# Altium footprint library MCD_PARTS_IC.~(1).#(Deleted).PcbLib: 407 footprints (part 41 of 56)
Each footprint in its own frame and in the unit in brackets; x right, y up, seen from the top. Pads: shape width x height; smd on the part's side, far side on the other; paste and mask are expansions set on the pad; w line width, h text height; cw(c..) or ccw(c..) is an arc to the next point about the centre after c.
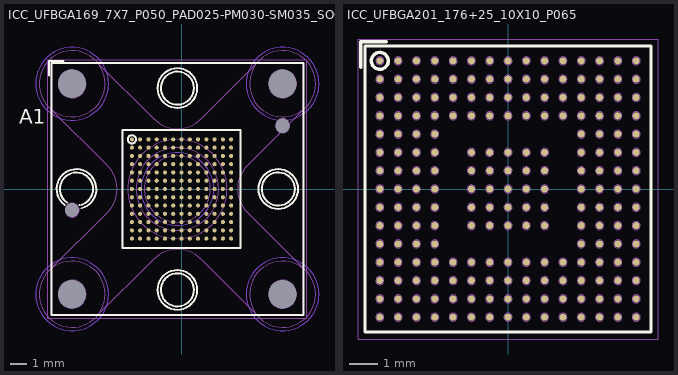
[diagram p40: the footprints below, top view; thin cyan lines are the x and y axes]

## ICC_UFBGA169_7X7_P050_PAD025-PM030-SM035_SOCKET_IRONWOOD_CS1627113MF_NM - duplicate1 [mm] "MCD-01902"
height 8.5
pads (175):
  round 0 hole 1.7 unplated mask+0.05: 0(-6.612,-6.362) 0(-6.612,6.363) 0(6.113,-6.362) 0(6.113,6.363)
  round 0 hole 0.85 unplated mask+0.05: 0(-6.612,-1.282) 0(6.113,3.823)
  round 0.25 smd paste+0.025 mask+0.05: A1(-3,3) A2(-2.5,3) A3(-2,3) A4(-1.5,3) A5(-1,3) A6(-0.5,3) A7(0,3) A8(0.5,3) A9(1,3) A10(1.5,3) A11(2,3) A12(2.5,3) A13(3,3) B1(-3,2.5) B2(-2.5,2.5) B3(-2,2.5) B4(-1.5,2.5) B5(-1,2.5) B6(-0.5,2.5) B7(0,2.5) B8(0.5,2.5) B9(1,2.5) B10(1.5,2.5) B11(2,2.5) B12(2.5,2.5) B13(3,2.5) C1(-3,2) C2(-2.5,2) C3(-2,2) C4(-1.5,2) C5(-1,2) C6(-0.5,2) C7(0,2) C8(0.5,2) C9(1,2) C10(1.5,2) C11(2,2) C12(2.5,2) C13(3,2) D1(-3,1.5) D2(-2.5,1.5) D3(-2,1.5) D4(-1.5,1.5) D5(-1,1.5) D6(-0.5,1.5) D7(0,1.5) D8(0.5,1.5) D9(1,1.5) D10(1.5,1.5) D11(2,1.5) D12(2.5,1.5) D13(3,1.5) E1(-3,1) E2(-2.5,1) E3(-2,1) E4(-1.5,1) E5(-1,1) E6(-0.5,1) E7(0,1) E8(0.5,1) E9(1,1) E10(1.5,1) E11(2,1) E12(2.5,1) E13(3,1) F1(-3,0.5) F2(-2.5,0.5) F3(-2,0.5) F4(-1.5,0.5) F5(-1,0.5) F6(-0.5,0.5) F7(0,0.5) F8(0.5,0.5) F9(1,0.5) F10(1.5,0.5) F11(2,0.5) F12(2.5,0.5) F13(3,0.5) G1(-3,0) G2(-2.5,0) G3(-2,0) G4(-1.5,0) G5(-1,0) G6(-0.5,0) G7(0,0) G8(0.5,0) G9(1,0) G10(1.5,0) G11(2,0) G12(2.5,0) G13(3,0) H1(-3,-0.5) H2(-2.5,-0.5) H3(-2,-0.5) H4(-1.5,-0.5) H5(-1,-0.5) H6(-0.5,-0.5) H7(0,-0.5) H8(0.5,-0.5) H9(1,-0.5) H10(1.5,-0.5) H11(2,-0.5) H12(2.5,-0.5) H13(3,-0.5) J1(-3,-1) J2(-2.5,-1) J3(-2,-1) J4(-1.5,-1) J5(-1,-1) J6(-0.5,-1) J7(0,-1) J8(0.5,-1) J9(1,-1) J10(1.5,-1) J11(2,-1) J12(2.5,-1) J13(3,-1) K1(-3,-1.5) K2(-2.5,-1.5) K3(-2,-1.5) K4(-1.5,-1.5) K5(-1,-1.5) K6(-0.5,-1.5) K7(0,-1.5) K8(0.5,-1.5) K9(1,-1.5) K10(1.5,-1.5) K11(2,-1.5) K12(2.5,-1.5) K13(3,-1.5) L1(-3,-2) L2(-2.5,-2) L3(-2,-2) L4(-1.5,-2) L5(-1,-2) L6(-0.5,-2) L7(0,-2) L8(0.5,-2) L9(1,-2) L10(1.5,-2) L11(2,-2) L12(2.5,-2) L13(3,-2) M1(-3,-2.5) M2(-2.5,-2.5) M3(-2,-2.5) M4(-1.5,-2.5) M5(-1,-2.5) M6(-0.5,-2.5) M7(0,-2.5) M8(0.5,-2.5) M9(1,-2.5) M10(1.5,-2.5) M11(2,-2.5) M12(2.5,-2.5) M13(3,-2.5) N1(-3,-3) N2(-2.5,-3) N3(-2,-3) N4(-1.5,-3) N5(-1,-3) N6(-0.5,-3) N7(0,-3) N8(0.5,-3) N9(1,-3) N10(1.5,-3) N11(2,-3) N12(2.5,-3) N13(3,-3)
Bottom Layer keep-out:
  circle w0.01: c-6.612,-6.362 r2.2
  circle w0.01: c6.113,-6.362 r2.2
  circle w0.01: c6.113,6.363 r2.2
  circle w0.01: c-0.25,0 r2.2
  circle w0.01: c-6.612,6.363 r2.2
Top Overlay:
  circle w0.12: c-0.25,-6.1 r1.2
  circle w0.12: c-0.25,-6.1 r1
  circle w0.12: c-0.25,6.1 r1.2
  circle w0.12: c-0.25,6.1 r1
  circle w0.12: c5.85,0 r1
  circle w0.12: c5.85,0 r1.2
  circle w0.12: c-3,3 r0.25
  circle w0.1: c-3,3 r0.25
  lines w0.12: -8,6.875 -8,7.75 -7.125,7.75 ; -7.066,-0.963 cw(c-6.35,0) -6.059,-1.164 ; -6.918,-0.823 cw(c-6.35,0) -6.154,-0.981 ; -7.862,-7.612 -7.862,7.613 7.363,7.613 7.363,-7.612 -7.862,-7.612 ; -3.575,-3.575 3.575,-3.575 3.575,3.575 -3.575,3.575 -3.575,-3.575
  text "A1" at -9.825,3.65 h1.5
Bottom Overlay:
  circle w0.12: c-6.612,6.363 r2
  circle w0.12: c6.113,6.363 r2
  circle w0.12: c-0.25,0 r2
  circle w0.12: c6.113,-6.362 r2
  circle w0.12: c-6.612,-6.362 r2
M6-Bottom Constraints:
  text "MAX / HEIGHT  / AUTHORIZED / 1.5mm" at 0,0 h0.8
  text "MAX / HEIGHT  / AUTHORIZED / 1.5mm" at 0,0 h0.8
  text "MAX / HEIGHT  / AUTHORIZED / 1.5mm" at 0,0 h0.8
  text "MAX / HEIGHT  / AUTHORIZED / 1.5mm" at 0,0 h0.8
M14-Top Assembly:
  circle w0.01: c-3,3 r0.25
  circle w0.01: c-0.25,0 r3
  circle w0.01: c-0.25,0 r2.5
  circle w0.01: c5.85,0 r1.2
  circle w0.01: c5.85,0 r1
  circle w0.01: c-0.25,6.1 r1
  circle w0.01: c-0.25,6.1 r1.2
  circle w0.01: c-6.35,0 r1
  circle w0.01: c-6.35,0 r1.2
  circle w0.01: c-0.25,-6.1 r1
  circle w0.01: c-0.25,-6.1 r1.2
  lines w0.01: -7.862,-7.612 7.363,-7.612 7.363,7.613 -7.862,7.613 -7.862,-7.612 ; -3.575,-3.575 -3.575,3.575 3.575,3.575 3.575,-3.575 -3.575,-3.575
  text "'.Designator'" at -2,-0.5 h0.75
  text "A1" at -3.4,3.05 h0.5
M15-Bottom Assembly:
  circle w0.01: c6.113,3.823 r0.425
  circle w0.01: c-6.612,-1.282 r0.425
  circle w0.01: c6.113,-6.362 r0.85
  circle w0.01: c-6.612,-6.362 r0.85
  circle w0.01: c6.113,6.363 r0.85
  circle w0.01: c-6.612,6.363 r0.85
  circle w0.01: c-0.25,0 r2
  circle w0.01: c-6.612,6.363 r2
  circle w0.01: c6.113,6.363 r2
  circle w0.01: c6.113,-6.362 r2
  circle w0.01: c-6.612,-6.362 r2
  lines w0.01: -7.862,4.8 -4.522,1.46 ; -5.05,-7.612 -1.71,-4.272 cw(c-0.25,-5.64) 1.21,-4.273 4.555,-7.617 ; -4.522,-1.46 -7.867,-4.805 ; -4.523,-1.46 ccw(c-5.89,0) -4.523,1.46 ; 4.022,-1.46 7.363,-4.8 ; 4.022,1.46 7.368,4.805 ; 4.023,-1.46 cw(c5.39,0) 4.023,1.46 ; 4.55,7.613 1.21,4.272 cw(c-0.25,5.64) -1.71,4.273 -5.055,7.618 ; -7.867,-4.805 -7.867,-4.805 ; -5.055,7.618 -5.055,7.618 ; 4.555,-7.617 4.555,-7.617 ; 7.368,4.805 7.368,4.805
M16-Top Courtyard:
  lines w0.01: -8.075,-7.825 -8.075,7.825 7.575,7.825 7.575,-7.825 -8.075,-7.825
M17-Bottom Courtyard:
  circle w0.01: c-6.612,-6.362 r2
  circle w0.01: c6.113,-6.362 r2
  circle w0.01: c6.113,6.363 r2
  circle w0.01: c-6.612,6.363 r2
  circle w0.01: c-0.25,0 r2
  lines w0.01: -7.862,4.8 -4.522,1.46 ; -5.05,-7.612 -1.71,-4.272 cw(c-0.25,-5.64) 1.21,-4.273 4.555,-7.617 ; -4.522,-1.46 -7.867,-4.805 ; -4.523,-1.46 ccw(c-5.89,0) -4.523,1.46 ; 4.022,-1.46 7.363,-4.8 ; 4.022,1.46 7.368,4.805 ; 4.023,-1.46 cw(c5.39,0) 4.023,1.46 ; 4.55,7.613 1.21,4.272 cw(c-0.25,5.64) -1.71,4.273 -5.055,7.618 ; -7.867,-4.805 -7.867,-4.805 ; -5.055,7.618 -5.055,7.618 ; 4.555,-7.617 4.555,-7.617 ; 7.368,4.805 7.368,4.805
  text "MAX / HEIGHT  / AUTHORIZED / 1.5mm" at 0,0 h0.8
  text "MAX / HEIGHT  / AUTHORIZED / 1.5mm" at 0,0 h0.8
  text "MAX / HEIGHT  / AUTHORIZED / 1.5mm" at 0,0 h0.8
  text "MAX / HEIGHT  / AUTHORIZED / 1.5mm" at 0,0 h0.8
3D body: height 0.61, standoff 0.6, extent -3.298,2.701 -2.7,3.299
3D body: height 0.25, standoff -0.05, extent -2.136,1.857 -1.855,2.143
3D body: height 0.25, standoff -0.05, extent -1.636,1.857 -1.355,2.143
3D body: height 0.25, standoff -0.05, extent -0.636,1.857 -0.355,2.143
3D body: height 0.25, standoff -0.05, extent -0.136,1.857 0.145,2.143
3D body: height 0.25, standoff -0.05, extent 0.864,1.857 1.145,2.143
3D body: height 0.25, standoff -0.05, extent 1.364,1.857 1.645,2.143
3D body: height 0.25, standoff -0.05, extent 1.864,1.857 2.145,2.143
3D body: height 0.25, standoff -0.05, extent -2.136,1.357 -1.855,1.643
3D body: height 0.25, standoff -0.05, extent -1.636,1.357 -1.355,1.643
3D body: height 0.25, standoff -0.05, extent -1.136,1.357 -0.855,1.643
3D body: height 0.25, standoff -0.05, extent -0.636,1.357 -0.355,1.643
3D body: height 0.25, standoff -0.05, extent -0.136,1.357 0.145,1.643
3D body: height 0.25, standoff -0.05, extent 0.364,1.357 0.645,1.643
3D body: height 0.25, standoff -0.05, extent 0.864,1.357 1.145,1.643
3D body: height 0.25, standoff -0.05, extent 1.364,1.357 1.645,1.643
3D body: height 0.25, standoff -0.05, extent 1.864,1.357 2.145,1.643
3D body: height 0.25, standoff -0.05, extent -1.136,0.857 -0.855,1.143
3D body: height 0.25, standoff -0.05, extent 0.364,0.857 0.645,1.143
3D body: height 0.25, standoff -0.05, extent 1.864,0.357 2.145,0.643
3D body: height 0.25, standoff -0.05, extent 1.364,0.357 1.645,0.643
3D body: height 0.25, standoff -0.05, extent 0.864,0.357 1.145,0.643
3D body: height 0.25, standoff -0.05, extent 0.364,0.357 0.645,0.643
3D body: height 0.25, standoff -0.05, extent -0.136,0.357 0.145,0.643
3D body: height 0.25, standoff -0.05, extent -0.636,0.357 -0.355,0.643
3D body: height 0.25, standoff -0.05, extent -1.136,0.357 -0.855,0.643
3D body: height 0.25, standoff -0.05, extent -1.636,0.357 -1.355,0.643
3D body: height 0.25, standoff -0.05, extent 1.364,0.857 1.645,1.143
3D body: height 0.25, standoff -0.05, extent 0.864,0.857 1.145,1.143
3D body: height 0.25, standoff -0.05, extent -0.136,0.857 0.145,1.143
3D body: height 0.25, standoff -0.05, extent -0.636,0.857 -0.355,1.143
3D body: height 0.25, standoff -0.05, extent -1.636,0.857 -1.355,1.143
3D body: height 0.25, standoff -0.05, extent -2.136,0.857 -1.855,1.143
3D body: height 0.25, standoff -0.05, extent -1.636,-1.143 -1.355,-0.857
3D body: height 0.25, standoff -0.05, extent -0.636,-1.143 -0.355,-0.857
3D body: height 0.25, standoff -0.05, extent -0.136,-1.143 0.145,-0.857
3D body: height 0.25, standoff -0.05, extent 0.864,-1.143 1.145,-0.857
3D body: height 0.25, standoff -0.05, extent 1.364,-1.143 1.645,-0.857
3D body: height 0.25, standoff -0.05, extent 1.864,-1.143 2.145,-0.857
3D body: height 0.25, standoff -0.05, extent -2.136,-1.643 -1.855,-1.357
3D body: height 0.25, standoff -0.05, extent -1.636,-1.643 -1.355,-1.357
3D body: height 0.25, standoff -0.05, extent -1.136,-1.643 -0.855,-1.357
3D body: height 0.25, standoff -0.05, extent -0.636,-1.643 -0.355,-1.357
3D body: height 0.25, standoff -0.05, extent -0.136,-1.643 0.145,-1.357
3D body: height 0.25, standoff -0.05, extent 0.364,-1.643 0.645,-1.357
3D body: height 0.25, standoff -0.05, extent 0.864,-1.643 1.145,-1.357
3D body: height 0.25, standoff -0.05, extent 1.364,-1.643 1.645,-1.357
3D body: height 0.25, standoff -0.05, extent 1.864,-1.643 2.145,-1.357
3D body: height 0.25, standoff -0.05, extent 0.364,-1.143 0.645,-0.857
3D body: height 0.25, standoff -0.05, extent -1.136,-1.143 -0.855,-0.857
3D body: height 0.25, standoff -0.05, extent -1.136,-0.143 -0.855,0.143
3D body: height 0.25, standoff -0.05, extent 0.364,-0.143 0.645,0.143
3D body: height 0.25, standoff -0.05, extent 1.364,-0.643 1.645,-0.357
3D body: height 0.25, standoff -0.05, extent 0.864,-0.643 1.145,-0.357
3D body: height 0.25, standoff -0.05, extent 0.364,-0.643 0.645,-0.357
3D body: height 0.25, standoff -0.05, extent -0.136,-0.643 0.145,-0.357
3D body: height 0.25, standoff -0.05, extent -0.636,-0.643 -0.355,-0.357
3D body: height 0.25, standoff -0.05, extent -1.136,-0.643 -0.855,-0.357
3D body: height 0.25, standoff -0.05, extent -1.636,-0.643 -1.355,-0.357
3D body: height 0.25, standoff -0.05, extent -2.136,-0.643 -1.855,-0.357
3D body: height 0.25, standoff -0.05, extent 1.864,-0.143 2.145,0.143
3D body: height 0.25, standoff -0.05, extent 1.364,-0.143 1.645,0.143
3D body: height 0.25, standoff -0.05, extent 0.864,-0.143 1.145,0.143
3D body: height 0.25, standoff -0.05, extent -0.136,-0.143 0.145,0.143
3D body: height 0.25, standoff -0.05, extent -0.636,-0.143 -0.355,0.143
3D body: height 0.25, standoff -0.05, extent -1.636,-0.143 -1.355,0.143
3D body: height 0.25, standoff -0.05, extent -2.136,-0.143 -1.855,0.143
3D body: height 0.25, standoff -0.05, extent 1.864,-2.143 2.145,-1.857
3D body: height 0.25, standoff -0.05, extent 1.364,-2.143 1.645,-1.857
3D body: height 0.25, standoff -0.05, extent 0.364,-2.143 0.645,-1.857
3D body: height 0.25, standoff -0.05, extent -0.136,-2.143 0.145,-1.857
3D body: height 0.25, standoff -0.05, extent -1.136,-2.143 -0.855,-1.857
3D body: height 0.25, standoff -0.05, extent -1.636,-2.143 -1.355,-1.857
3D body: height 0.25, standoff -0.05, extent -2.136,-2.143 -1.855,-1.857
3D body: height 0.25, standoff -0.05, extent -1.136,1.857 -0.855,2.143
3D body: height 0.25, standoff -0.05, extent 0.364,1.857 0.645,2.143
3D body: height 0.25, standoff -0.05, extent -2.136,0.357 -1.855,0.643
3D body: height 0.25, standoff -0.05, extent 1.864,0.857 2.145,1.143
3D body: height 0.25, standoff -0.05, extent 1.864,-0.643 2.145,-0.357
3D body: height 0.25, standoff -0.05, extent -2.136,-1.143 -1.855,-0.857
3D body: height 0.25, standoff -0.05, extent -2.636,1.857 -2.355,2.143
3D body: height 0.25, standoff -0.05, extent -3.136,1.857 -2.855,2.143
3D body: height 0.25, standoff -0.05, extent 2.364,1.857 2.645,2.143
3D body: height 0.25, standoff -0.05, extent 2.864,1.857 3.145,2.143
3D body: height 0.25, standoff -0.05, extent -0.136,2.357 0.145,2.643
3D body: height 0.25, standoff -0.05, extent -0.136,2.857 0.145,3.143
3D body: height 0.25, standoff -0.05, extent -0.136,-2.643 0.145,-2.357
3D body: height 0.25, standoff -0.05, extent -0.136,-3.143 0.145,-2.857
3D body: height 0.25, standoff -0.05, extent -0.636,-2.143 -0.355,-1.857
3D body: height 0.25, standoff -0.05, extent 0.864,-2.143 1.145,-1.857
3D body: height 0.25, standoff -0.05, extent 2.864,1.357 3.145,1.643
3D body: height 0.25, standoff -0.05, extent 2.364,1.357 2.645,1.643
3D body: height 0.25, standoff -0.05, extent 2.864,0.857 3.145,1.143
3D body: height 0.25, standoff -0.05, extent 2.364,0.857 2.645,1.143
3D body: height 0.25, standoff -0.05, extent 2.864,0.357 3.145,0.643
3D body: height 0.25, standoff -0.05, extent 2.364,0.357 2.645,0.643
3D body: height 0.25, standoff -0.05, extent 2.864,-0.143 3.145,0.143
3D body: height 0.25, standoff -0.05, extent 2.364,-0.143 2.645,0.143
3D body: height 0.25, standoff -0.05, extent 2.864,-0.643 3.145,-0.357
3D body: height 0.25, standoff -0.05, extent 2.364,-0.643 2.645,-0.357
3D body: height 0.25, standoff -0.05, extent 2.864,-1.143 3.145,-0.857
3D body: height 0.25, standoff -0.05, extent 2.364,-1.143 2.645,-0.857
3D body: height 0.25, standoff -0.05, extent 2.864,-1.643 3.145,-1.357
3D body: height 0.25, standoff -0.05, extent 2.364,-1.643 2.645,-1.357
3D body: height 0.25, standoff -0.05, extent 2.864,-2.143 3.145,-1.857
3D body: height 0.25, standoff -0.05, extent 2.364,-2.143 2.645,-1.857
3D body: height 0.25, standoff -0.05, extent -2.636,1.357 -2.355,1.643
3D body: height 0.25, standoff -0.05, extent -3.136,1.357 -2.855,1.643
3D body: height 0.25, standoff -0.05, extent -2.636,0.857 -2.355,1.143
3D body: height 0.25, standoff -0.05, extent -3.136,0.857 -2.855,1.143
3D body: height 0.25, standoff -0.05, extent -2.636,0.357 -2.355,0.643
3D body: height 0.25, standoff -0.05, extent -3.136,0.357 -2.855,0.643
3D body: height 0.25, standoff -0.05, extent -2.636,-0.143 -2.355,0.143
3D body: height 0.25, standoff -0.05, extent -3.136,-0.143 -2.855,0.143
3D body: height 0.25, standoff -0.05, extent -2.636,-0.643 -2.355,-0.357
3D body: height 0.25, standoff -0.05, extent -3.136,-0.643 -2.855,-0.357
3D body: height 0.25, standoff -0.05, extent -2.636,-1.143 -2.355,-0.857
3D body: height 0.25, standoff -0.05, extent -3.136,-1.143 -2.855,-0.857
3D body: height 0.25, standoff -0.05, extent -2.636,-1.643 -2.355,-1.357
3D body: height 0.25, standoff -0.05, extent -3.136,-1.643 -2.855,-1.357
3D body: height 0.25, standoff -0.05, extent -2.636,-2.143 -2.355,-1.857
3D body: height 0.25, standoff -0.05, extent -3.136,-2.143 -2.855,-1.857
3D body: height 0.25, standoff -0.05, extent -3.136,2.357 -2.855,2.643
3D body: height 0.25, standoff -0.05, extent -2.636,2.357 -2.355,2.643
3D body: height 0.25, standoff -0.05, extent -1.136,2.357 -0.855,2.643
3D body: height 0.25, standoff -0.05, extent -0.636,2.357 -0.355,2.643
3D body: height 0.25, standoff -0.05, extent -1.636,2.357 -1.355,2.643
3D body: height 0.25, standoff -0.05, extent -2.136,2.357 -1.855,2.643
3D body: height 0.25, standoff -0.05, extent -3.136,2.857 -2.855,3.143
3D body: height 0.25, standoff -0.05, extent -2.636,2.857 -2.355,3.143
3D body: height 0.25, standoff -0.05, extent -1.136,2.857 -0.855,3.143
3D body: height 0.25, standoff -0.05, extent -0.636,2.857 -0.355,3.143
3D body: height 0.25, standoff -0.05, extent -1.636,2.857 -1.355,3.143
3D body: height 0.25, standoff -0.05, extent -2.136,2.857 -1.855,3.143
3D body: height 0.25, standoff -0.05, extent 0.364,2.357 0.645,2.643
3D body: height 0.25, standoff -0.05, extent 0.864,2.357 1.145,2.643
3D body: height 0.25, standoff -0.05, extent 2.364,2.357 2.645,2.643
3D body: height 0.25, standoff -0.05, extent 2.864,2.357 3.145,2.643
3D body: height 0.25, standoff -0.05, extent 1.864,2.357 2.145,2.643
3D body: height 0.25, standoff -0.05, extent 1.364,2.357 1.645,2.643
3D body: height 0.25, standoff -0.05, extent 0.364,2.857 0.645,3.143
3D body: height 0.25, standoff -0.05, extent 0.864,2.857 1.145,3.143
3D body: height 0.25, standoff -0.05, extent 2.364,2.857 2.645,3.143
3D body: height 0.25, standoff -0.05, extent 2.864,2.857 3.145,3.143
3D body: height 0.25, standoff -0.05, extent 1.864,2.857 2.145,3.143
3D body: height 0.25, standoff -0.05, extent 1.364,2.857 1.645,3.143
3D body: height 0.25, standoff -0.05, extent -3.136,-2.643 -2.855,-2.357
3D body: height 0.25, standoff -0.05, extent -2.636,-2.643 -2.355,-2.357
3D body: height 0.25, standoff -0.05, extent -1.136,-2.643 -0.855,-2.357
3D body: height 0.25, standoff -0.05, extent -0.636,-2.643 -0.355,-2.357
3D body: height 0.25, standoff -0.05, extent -1.636,-2.643 -1.355,-2.357
3D body: height 0.25, standoff -0.05, extent -2.136,-2.643 -1.855,-2.357
3D body: height 0.25, standoff -0.05, extent -3.136,-3.143 -2.855,-2.857
3D body: height 0.25, standoff -0.05, extent -2.636,-3.143 -2.355,-2.857
3D body: height 0.25, standoff -0.05, extent -1.136,-3.143 -0.855,-2.857
3D body: height 0.25, standoff -0.05, extent -0.636,-3.143 -0.355,-2.857
3D body: height 0.25, standoff -0.05, extent -1.636,-3.143 -1.355,-2.857
3D body: height 0.25, standoff -0.05, extent -2.136,-3.143 -1.855,-2.857
3D body: height 0.25, standoff -0.05, extent 0.364,-2.643 0.645,-2.357
3D body: height 0.25, standoff -0.05, extent 0.864,-2.643 1.145,-2.357
3D body: height 0.25, standoff -0.05, extent 2.364,-2.643 2.645,-2.357
3D body: height 0.25, standoff -0.05, extent 2.864,-2.643 3.145,-2.357
3D body: height 0.25, standoff -0.05, extent 1.864,-2.643 2.145,-2.357
3D body: height 0.25, standoff -0.05, extent 1.364,-2.643 1.645,-2.357
3D body: height 0.25, standoff -0.05, extent 0.364,-3.143 0.645,-2.857
3D body: height 0.25, standoff -0.05, extent 0.864,-3.143 1.145,-2.857
3D body: height 0.25, standoff -0.05, extent 2.364,-3.143 2.645,-2.857
3D body: height 0.25, standoff -0.05, extent 2.864,-3.143 3.145,-2.857
3D body: height 0.25, standoff -0.05, extent 1.864,-3.143 2.145,-2.857
3D body: height 0.25, standoff -0.05, extent 1.364,-3.143 1.645,-2.857
3D body: height 0.6, standoff 0.15, extent -3.5,-3.5 3.5,3.5

## ICC_UFBGA201_176+25_10X10_P065 [mm]
height 0.6
pads (201):
  round 0.25 smd mask+0.038: A1(-4.55,4.55) A2(-3.9,4.55) A3(-3.25,4.55) A4(-2.6,4.55) A5(-1.95,4.55) A6(-1.3,4.55) A7(-0.65,4.55) A8(0,4.55) A9(0.65,4.55) A10(1.3,4.55) A11(1.95,4.55) A12(2.6,4.55) A13(3.25,4.55) A14(3.9,4.55) A15(4.55,4.55) B1(-4.55,3.9) B2(-3.9,3.9) B3(-3.25,3.9) B4(-2.6,3.9) B5(-1.95,3.9) B6(-1.3,3.9) B7(-0.65,3.9) B8(0,3.9) B9(0.65,3.9) B10(1.3,3.9) B11(1.95,3.9) B12(2.6,3.9) B13(3.25,3.9) B14(3.9,3.9) B15(4.55,3.9) C1(-4.55,3.25) C2(-3.9,3.25) C3(-3.25,3.25) C4(-2.6,3.25) C5(-1.95,3.25) C6(-1.3,3.25) C7(-0.65,3.25) C8(0,3.25) C9(0.65,3.25) C10(1.3,3.25) C11(1.95,3.25) C12(2.6,3.25) C13(3.25,3.25) C14(3.9,3.25) C15(4.55,3.25) D1(-4.55,2.6) D2(-3.9,2.6) D3(-3.25,2.6) D4(-2.6,2.6) D5(-1.95,2.6) D6(-1.3,2.6) D7(-0.65,2.6) D8(0,2.6) D9(0.65,2.6) D10(1.3,2.6) D11(1.95,2.6) D12(2.6,2.6) D13(3.25,2.6) D14(3.9,2.6) D15(4.55,2.6) E1(-4.55,1.95) E2(-3.9,1.95) E3(-3.25,1.95) E4(-2.6,1.95) E12(2.6,1.95) E13(3.25,1.95) E14(3.9,1.95) E15(4.55,1.95) F1(-4.55,1.3) F2(-3.9,1.3) F3(-3.25,1.3) F4(-2.6,1.3) F6(-1.3,1.3) F7(-0.65,1.3) F8(0,1.3) F9(0.65,1.3) F10(1.3,1.3) F12(2.6,1.3) F13(3.25,1.3) F14(3.9,1.3) F15(4.55,1.3) G1(-4.55,0.65) G2(-3.9,0.65) G3(-3.25,0.65) G4(-2.6,0.65) G6(-1.3,0.65) G7(-0.65,0.65) G8(0,0.65) G9(0.65,0.65) G10(1.3,0.65) G12(2.6,0.65) G13(3.25,0.65) G14(3.9,0.65) G15(4.55,0.65) H1(-4.55,0) H2(-3.9,0) H3(-3.25,0) H4(-2.6,0) H6(-1.3,0) H7(-0.65,0) H8(0,0) H9(0.65,0) H10(1.3,0) H12(2.6,0) H13(3.25,0) H14(3.9,0) H15(4.55,0) J1(-4.55,-0.65) J2(-3.9,-0.65) J3(-3.25,-0.65) J4(-2.6,-0.65) J6(-1.3,-0.65) J7(-0.65,-0.65) J8(0,-0.65) J9(0.65,-0.65) J10(1.3,-0.65) J12(2.6,-0.65) J13(3.25,-0.65) J14(3.9,-0.65) J15(4.55,-0.65) K1(-4.55,-1.3) K2(-3.9,-1.3) K3(-3.25,-1.3) K4(-2.6,-1.3) K6(-1.3,-1.3) K7(-0.65,-1.3) K8(0,-1.3) K9(0.65,-1.3) K10(1.3,-1.3) K12(2.6,-1.3) K13(3.25,-1.3) K14(3.9,-1.3) K15(4.55,-1.3) L1(-4.55,-1.95) L2(-3.9,-1.95) L3(-3.25,-1.95) L4(-2.6,-1.95) L12(2.6,-1.95) L13(3.25,-1.95) L14(3.9,-1.95) L15(4.55,-1.95) M1(-4.55,-2.6) M2(-3.9,-2.6) M3(-3.25,-2.6) M4(-2.6,-2.6) M5(-1.95,-2.6) M6(-1.3,-2.6) M7(-0.65,-2.6) M8(0,-2.6) M9(0.65,-2.6) M10(1.3,-2.6) M11(1.95,-2.6) M12(2.6,-2.6) M13(3.25,-2.6) M14(3.9,-2.6) M15(4.55,-2.6) N1(-4.55,-3.25) N2(-3.9,-3.25) N3(-3.25,-3.25) N4(-2.6,-3.25) N5(-1.95,-3.25) N6(-1.3,-3.25) N7(-0.65,-3.25) N8(0,-3.25) N9(0.65,-3.25) N10(1.3,-3.25) N11(1.95,-3.25) N12(2.6,-3.25) N13(3.25,-3.25) N14(3.9,-3.25) N15(4.55,-3.25) P1(-4.55,-3.9) P2(-3.9,-3.9) P3(-3.25,-3.9) P4(-2.6,-3.9) P5(-1.95,-3.9) P6(-1.3,-3.9) P7(-0.65,-3.9) P8(0,-3.9) P9(0.65,-3.9) P10(1.3,-3.9) P11(1.95,-3.9) P12(2.6,-3.9) P13(3.25,-3.9) P14(3.9,-3.9) P15(4.55,-3.9) R1(-4.55,-4.55) R2(-3.9,-4.55) R3(-3.25,-4.55) R4(-2.6,-4.55) R5(-1.95,-4.55) R6(-1.3,-4.55) R7(-0.65,-4.55) R8(0,-4.55) R9(0.65,-4.55) R10(1.3,-4.55) R11(1.95,-4.55) R12(2.6,-4.55) R13(3.25,-4.55) R14(3.9,-4.55) R15(4.55,-4.55)
Top Overlay:
  circle w0.12: c-4.55,4.55 r0.3
  lines w0.12: -5.225,4.325 -5.225,5.225 -4.325,5.225 ; -5.075,-5.075 5.075,-5.075 5.075,5.075 -5.075,5.075 -5.075,-5.075
M14-Top Assembly:
  drawing of 205 lines, arcs and shapes, not listed
  text "A1" at -4.9,4.4 h0.75
  text "'.Designator'" at 0,0 h0.75
M16-Top Courtyard:
  lines w0.01: -5.325,-5.325 5.325,-5.325 5.325,5.325 -5.325,5.325 -5.325,-5.325
3D body: height 0.61, standoff 0.6, extent -4.798,4.301 -4.3,4.8
3D body: height 0.6, standoff 0.15, extent -5.075,-5.075 5.075,5.075
3D body: height 0.25, standoff -0.05, extent -4.036,4.407 -3.755,4.693
3D body: height 0.25, standoff -0.05, extent -4.686,4.407 -4.405,4.693
3D body: height 0.25, standoff -0.05, extent -3.386,4.407 -3.105,4.693
3D body: height 0.25, standoff -0.05, extent -2.736,4.407 -2.455,4.693
3D body: height 0.25, standoff -0.05, extent -2.086,4.407 -1.805,4.693
3D body: height 0.25, standoff -0.05, extent -1.436,4.407 -1.155,4.693
3D body: height 0.25, standoff -0.05, extent -0.786,4.407 -0.505,4.693
3D body: height 0.25, standoff -0.05, extent -0.136,4.407 0.145,4.693
3D body: height 0.25, standoff -0.05, extent 0.514,4.407 0.795,4.693
3D body: height 0.25, standoff -0.05, extent 1.164,4.407 1.445,4.693
3D body: height 0.25, standoff -0.05, extent 1.814,4.407 2.095,4.693
3D body: height 0.25, standoff -0.05, extent 2.464,4.407 2.745,4.693
3D body: height 0.25, standoff -0.05, extent 3.114,4.407 3.395,4.693
3D body: height 0.25, standoff -0.05, extent 3.764,4.407 4.045,4.693
3D body: height 0.25, standoff -0.05, extent 4.414,4.407 4.695,4.693
3D body: height 0.25, standoff -0.05, extent 4.414,3.757 4.695,4.043
3D body: height 0.25, standoff -0.05, extent 3.764,3.757 4.045,4.043
3D body: height 0.25, standoff -0.05, extent 3.114,3.757 3.395,4.043
3D body: height 0.25, standoff -0.05, extent 2.464,3.757 2.745,4.043
3D body: height 0.25, standoff -0.05, extent 1.814,3.757 2.095,4.043
3D body: height 0.25, standoff -0.05, extent 1.164,3.757 1.445,4.043
3D body: height 0.25, standoff -0.05, extent 0.514,3.757 0.795,4.043
3D body: height 0.25, standoff -0.05, extent -0.136,3.757 0.145,4.043
3D body: height 0.25, standoff -0.05, extent -0.786,3.757 -0.505,4.043
3D body: height 0.25, standoff -0.05, extent -1.436,3.757 -1.155,4.043
3D body: height 0.25, standoff -0.05, extent -2.086,3.757 -1.805,4.043
3D body: height 0.25, standoff -0.05, extent -2.736,3.757 -2.455,4.043
3D body: height 0.25, standoff -0.05, extent -3.386,3.757 -3.105,4.043
3D body: height 0.25, standoff -0.05, extent -4.686,3.757 -4.405,4.043
3D body: height 0.25, standoff -0.05, extent -4.036,3.757 -3.755,4.043
3D body: height 0.25, standoff -0.05, extent 4.414,3.107 4.695,3.393
3D body: height 0.25, standoff -0.05, extent 3.764,3.107 4.045,3.393
3D body: height 0.25, standoff -0.05, extent 3.114,3.107 3.395,3.393
3D body: height 0.25, standoff -0.05, extent 2.464,3.107 2.745,3.393
3D body: height 0.25, standoff -0.05, extent 1.814,3.107 2.095,3.393
3D body: height 0.25, standoff -0.05, extent 1.164,3.107 1.445,3.393
3D body: height 0.25, standoff -0.05, extent 0.514,3.107 0.795,3.393
3D body: height 0.25, standoff -0.05, extent -0.136,3.107 0.145,3.393
3D body: height 0.25, standoff -0.05, extent -0.786,3.107 -0.505,3.393
3D body: height 0.25, standoff -0.05, extent -1.436,3.107 -1.155,3.393
3D body: height 0.25, standoff -0.05, extent -2.086,3.107 -1.805,3.393
3D body: height 0.25, standoff -0.05, extent -2.736,3.107 -2.455,3.393
3D body: height 0.25, standoff -0.05, extent -3.386,3.107 -3.105,3.393
3D body: height 0.25, standoff -0.05, extent -4.686,3.107 -4.405,3.393
3D body: height 0.25, standoff -0.05, extent -4.036,3.107 -3.755,3.393
3D body: height 0.25, standoff -0.05, extent 4.414,2.457 4.695,2.743
3D body: height 0.25, standoff -0.05, extent 3.764,2.457 4.045,2.743
3D body: height 0.25, standoff -0.05, extent 3.114,2.457 3.395,2.743
3D body: height 0.25, standoff -0.05, extent 2.464,2.457 2.745,2.743
3D body: height 0.25, standoff -0.05, extent 1.814,2.457 2.095,2.743
3D body: height 0.25, standoff -0.05, extent 1.164,2.457 1.445,2.743
3D body: height 0.25, standoff -0.05, extent 0.514,2.457 0.795,2.743
3D body: height 0.25, standoff -0.05, extent -0.136,2.457 0.145,2.743
3D body: height 0.25, standoff -0.05, extent -0.786,2.457 -0.505,2.743
3D body: height 0.25, standoff -0.05, extent -1.436,2.457 -1.155,2.743
3D body: height 0.25, standoff -0.05, extent -2.086,2.457 -1.805,2.743
3D body: height 0.25, standoff -0.05, extent -2.736,2.457 -2.455,2.743
3D body: height 0.25, standoff -0.05, extent -3.386,2.457 -3.105,2.743
3D body: height 0.25, standoff -0.05, extent -4.686,2.457 -4.405,2.743
3D body: height 0.25, standoff -0.05, extent -4.036,2.457 -3.755,2.743
3D body: height 0.25, standoff -0.05, extent 4.414,1.807 4.695,2.093
3D body: height 0.25, standoff -0.05, extent 3.764,1.807 4.045,2.093
3D body: height 0.25, standoff -0.05, extent 3.114,1.807 3.395,2.093
3D body: height 0.25, standoff -0.05, extent 2.464,1.807 2.745,2.093
3D body: height 0.25, standoff -0.05, extent -2.736,1.807 -2.455,2.093
3D body: height 0.25, standoff -0.05, extent -3.386,1.807 -3.105,2.093
3D body: height 0.25, standoff -0.05, extent -4.686,1.807 -4.405,2.093
3D body: height 0.25, standoff -0.05, extent -4.036,1.807 -3.755,2.093
3D body: height 0.25, standoff -0.05, extent -4.036,-1.443 -3.755,-1.157
3D body: height 0.25, standoff -0.05, extent -4.686,-1.443 -4.405,-1.157
3D body: height 0.25, standoff -0.05, extent -3.386,-1.443 -3.105,-1.157
3D body: height 0.25, standoff -0.05, extent -2.736,-1.443 -2.455,-1.157
3D body: height 0.25, standoff -0.05, extent -1.436,-1.443 -1.155,-1.157
3D body: height 0.25, standoff -0.05, extent -0.786,-1.443 -0.505,-1.157
3D body: height 0.25, standoff -0.05, extent -0.136,-1.443 0.145,-1.157
3D body: height 0.25, standoff -0.05, extent 0.514,-1.443 0.795,-1.157
3D body: height 0.25, standoff -0.05, extent 1.164,-1.443 1.445,-1.157
3D body: height 0.25, standoff -0.05, extent 2.464,-1.443 2.745,-1.157
3D body: height 0.25, standoff -0.05, extent 3.114,-1.443 3.395,-1.157
3D body: height 0.25, standoff -0.05, extent 3.764,-1.443 4.045,-1.157
3D body: height 0.25, standoff -0.05, extent 4.414,-1.443 4.695,-1.157
3D body: height 0.25, standoff -0.05, extent -4.036,-0.793 -3.755,-0.507
3D body: height 0.25, standoff -0.05, extent -4.686,-0.793 -4.405,-0.507
3D body: height 0.25, standoff -0.05, extent -3.386,-0.793 -3.105,-0.507
3D body: height 0.25, standoff -0.05, extent -2.736,-0.793 -2.455,-0.507
3D body: height 0.25, standoff -0.05, extent -1.436,-0.793 -1.155,-0.507
3D body: height 0.25, standoff -0.05, extent -0.786,-0.793 -0.505,-0.507
3D body: height 0.25, standoff -0.05, extent -0.136,-0.793 0.145,-0.507
3D body: height 0.25, standoff -0.05, extent 0.514,-0.793 0.795,-0.507
3D body: height 0.25, standoff -0.05, extent 1.164,-0.793 1.445,-0.507
3D body: height 0.25, standoff -0.05, extent 2.464,-0.793 2.745,-0.507
3D body: height 0.25, standoff -0.05, extent 3.114,-0.793 3.395,-0.507
3D body: height 0.25, standoff -0.05, extent 3.764,-0.793 4.045,-0.507
3D body: height 0.25, standoff -0.05, extent 4.414,-0.793 4.695,-0.507
3D body: height 0.25, standoff -0.05, extent -4.036,-0.143 -3.755,0.143
3D body: height 0.25, standoff -0.05, extent -4.686,-0.143 -4.405,0.143
3D body: height 0.25, standoff -0.05, extent -3.386,-0.143 -3.105,0.143
3D body: height 0.25, standoff -0.05, extent -2.736,-0.143 -2.455,0.143
3D body: height 0.25, standoff -0.05, extent -1.436,-0.143 -1.155,0.143
3D body: height 0.25, standoff -0.05, extent -0.786,-0.143 -0.505,0.143
3D body: height 0.25, standoff -0.05, extent -0.136,-0.143 0.145,0.143
3D body: height 0.25, standoff -0.05, extent 0.514,-0.143 0.795,0.143
3D body: height 0.25, standoff -0.05, extent 1.164,-0.143 1.445,0.143
3D body: height 0.25, standoff -0.05, extent 2.464,-0.143 2.745,0.143
3D body: height 0.25, standoff -0.05, extent 3.114,-0.143 3.395,0.143
3D body: height 0.25, standoff -0.05, extent 3.764,-0.143 4.045,0.143
3D body: height 0.25, standoff -0.05, extent 4.414,-0.143 4.695,0.143
3D body: height 0.25, standoff -0.05, extent -4.036,0.507 -3.755,0.793
3D body: height 0.25, standoff -0.05, extent -4.686,0.507 -4.405,0.793
3D body: height 0.25, standoff -0.05, extent -3.386,0.507 -3.105,0.793
3D body: height 0.25, standoff -0.05, extent -2.736,0.507 -2.455,0.793
3D body: height 0.25, standoff -0.05, extent -1.436,0.507 -1.155,0.793
3D body: height 0.25, standoff -0.05, extent -0.786,0.507 -0.505,0.793
3D body: height 0.25, standoff -0.05, extent -0.136,0.507 0.145,0.793
3D body: height 0.25, standoff -0.05, extent 0.514,0.507 0.795,0.793
3D body: height 0.25, standoff -0.05, extent 1.164,0.507 1.445,0.793
3D body: height 0.25, standoff -0.05, extent 2.464,0.507 2.745,0.793
3D body: height 0.25, standoff -0.05, extent 3.114,0.507 3.395,0.793
3D body: height 0.25, standoff -0.05, extent 3.764,0.507 4.045,0.793
3D body: height 0.25, standoff -0.05, extent 4.414,0.507 4.695,0.793
3D body: height 0.25, standoff -0.05, extent 4.414,1.157 4.695,1.443
3D body: height 0.25, standoff -0.05, extent 3.764,1.157 4.045,1.443
3D body: height 0.25, standoff -0.05, extent 3.114,1.157 3.395,1.443
3D body: height 0.25, standoff -0.05, extent 2.464,1.157 2.745,1.443
3D body: height 0.25, standoff -0.05, extent 1.164,1.157 1.445,1.443
3D body: height 0.25, standoff -0.05, extent 0.514,1.157 0.795,1.443
3D body: height 0.25, standoff -0.05, extent -0.136,1.157 0.145,1.443
3D body: height 0.25, standoff -0.05, extent -0.786,1.157 -0.505,1.443
3D body: height 0.25, standoff -0.05, extent -1.436,1.157 -1.155,1.443
3D body: height 0.25, standoff -0.05, extent -2.736,1.157 -2.455,1.443
3D body: height 0.25, standoff -0.05, extent -3.386,1.157 -3.105,1.443
3D body: height 0.25, standoff -0.05, extent -4.686,1.157 -4.405,1.443
3D body: height 0.25, standoff -0.05, extent -4.036,1.157 -3.755,1.443
3D body: height 0.25, standoff -0.05, extent -4.036,-4.693 -3.755,-4.407
3D body: height 0.25, standoff -0.05, extent -4.686,-4.693 -4.405,-4.407
3D body: height 0.25, standoff -0.05, extent -3.386,-4.693 -3.105,-4.407
3D body: height 0.25, standoff -0.05, extent -2.736,-4.693 -2.455,-4.407
3D body: height 0.25, standoff -0.05, extent -2.086,-4.693 -1.805,-4.407
3D body: height 0.25, standoff -0.05, extent -1.436,-4.693 -1.155,-4.407
3D body: height 0.25, standoff -0.05, extent -0.786,-4.693 -0.505,-4.407
3D body: height 0.25, standoff -0.05, extent -0.136,-4.693 0.145,-4.407
3D body: height 0.25, standoff -0.05, extent 0.514,-4.693 0.795,-4.407
3D body: height 0.25, standoff -0.05, extent 1.164,-4.693 1.445,-4.407
3D body: height 0.25, standoff -0.05, extent 1.814,-4.693 2.095,-4.407
3D body: height 0.25, standoff -0.05, extent 2.464,-4.693 2.745,-4.407
3D body: height 0.25, standoff -0.05, extent 3.114,-4.693 3.395,-4.407
3D body: height 0.25, standoff -0.05, extent 3.764,-4.693 4.045,-4.407
3D body: height 0.25, standoff -0.05, extent 4.414,-4.693 4.695,-4.407
3D body: height 0.25, standoff -0.05, extent -4.036,-4.043 -3.755,-3.757
3D body: height 0.25, standoff -0.05, extent -4.686,-4.043 -4.405,-3.757
3D body: height 0.25, standoff -0.05, extent -3.386,-4.043 -3.105,-3.757
3D body: height 0.25, standoff -0.05, extent -2.736,-4.043 -2.455,-3.757
3D body: height 0.25, standoff -0.05, extent -2.086,-4.043 -1.805,-3.757
3D body: height 0.25, standoff -0.05, extent -1.436,-4.043 -1.155,-3.757
3D body: height 0.25, standoff -0.05, extent -0.786,-4.043 -0.505,-3.757
3D body: height 0.25, standoff -0.05, extent -0.136,-4.043 0.145,-3.757
3D body: height 0.25, standoff -0.05, extent 0.514,-4.043 0.795,-3.757
3D body: height 0.25, standoff -0.05, extent 1.164,-4.043 1.445,-3.757
3D body: height 0.25, standoff -0.05, extent 1.814,-4.043 2.095,-3.757
3D body: height 0.25, standoff -0.05, extent 2.464,-4.043 2.745,-3.757
3D body: height 0.25, standoff -0.05, extent 3.114,-4.043 3.395,-3.757
3D body: height 0.25, standoff -0.05, extent 3.764,-4.043 4.045,-3.757
3D body: height 0.25, standoff -0.05, extent 4.414,-4.043 4.695,-3.757
3D body: height 0.25, standoff -0.05, extent -4.036,-3.393 -3.755,-3.107
3D body: height 0.25, standoff -0.05, extent -4.686,-3.393 -4.405,-3.107
3D body: height 0.25, standoff -0.05, extent -3.386,-3.393 -3.105,-3.107
3D body: height 0.25, standoff -0.05, extent -2.736,-3.393 -2.455,-3.107
3D body: height 0.25, standoff -0.05, extent -2.086,-3.393 -1.805,-3.107
3D body: height 0.25, standoff -0.05, extent -1.436,-3.393 -1.155,-3.107
3D body: height 0.25, standoff -0.05, extent -0.786,-3.393 -0.505,-3.107
3D body: height 0.25, standoff -0.05, extent -0.136,-3.393 0.145,-3.107
3D body: height 0.25, standoff -0.05, extent 0.514,-3.393 0.795,-3.107
3D body: height 0.25, standoff -0.05, extent 1.164,-3.393 1.445,-3.107
3D body: height 0.25, standoff -0.05, extent 1.814,-3.393 2.095,-3.107
3D body: height 0.25, standoff -0.05, extent 2.464,-3.393 2.745,-3.107
3D body: height 0.25, standoff -0.05, extent 3.114,-3.393 3.395,-3.107
3D body: height 0.25, standoff -0.05, extent 3.764,-3.393 4.045,-3.107
3D body: height 0.25, standoff -0.05, extent 4.414,-3.393 4.695,-3.107
3D body: height 0.25, standoff -0.05, extent -4.036,-2.743 -3.755,-2.457
3D body: height 0.25, standoff -0.05, extent -4.686,-2.743 -4.405,-2.457
3D body: height 0.25, standoff -0.05, extent -3.386,-2.743 -3.105,-2.457
3D body: height 0.25, standoff -0.05, extent -2.736,-2.743 -2.455,-2.457
3D body: height 0.25, standoff -0.05, extent -2.086,-2.743 -1.805,-2.457
3D body: height 0.25, standoff -0.05, extent -1.436,-2.743 -1.155,-2.457
3D body: height 0.25, standoff -0.05, extent -0.786,-2.743 -0.505,-2.457
3D body: height 0.25, standoff -0.05, extent -0.136,-2.743 0.145,-2.457
3D body: height 0.25, standoff -0.05, extent 0.514,-2.743 0.795,-2.457
3D body: height 0.25, standoff -0.05, extent 1.164,-2.743 1.445,-2.457
3D body: height 0.25, standoff -0.05, extent 1.814,-2.743 2.095,-2.457
3D body: height 0.25, standoff -0.05, extent 2.464,-2.743 2.745,-2.457
3D body: height 0.25, standoff -0.05, extent 3.114,-2.743 3.395,-2.457
3D body: height 0.25, standoff -0.05, extent 3.764,-2.743 4.045,-2.457
3D body: height 0.25, standoff -0.05, extent 4.414,-2.743 4.695,-2.457
3D body: height 0.25, standoff -0.05, extent 4.414,-2.093 4.695,-1.807
3D body: height 0.25, standoff -0.05, extent 3.764,-2.093 4.045,-1.807
3D body: height 0.25, standoff -0.05, extent 3.114,-2.093 3.395,-1.807
3D body: height 0.25, standoff -0.05, extent 2.464,-2.093 2.745,-1.807
3D body: height 0.25, standoff -0.05, extent -2.736,-2.093 -2.455,-1.807
3D body: height 0.25, standoff -0.05, extent -3.386,-2.093 -3.105,-1.807
3D body: height 0.25, standoff -0.05, extent -4.686,-2.093 -4.405,-1.807
3D body: height 0.25, standoff -0.05, extent -4.036,-2.093 -3.755,-1.807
